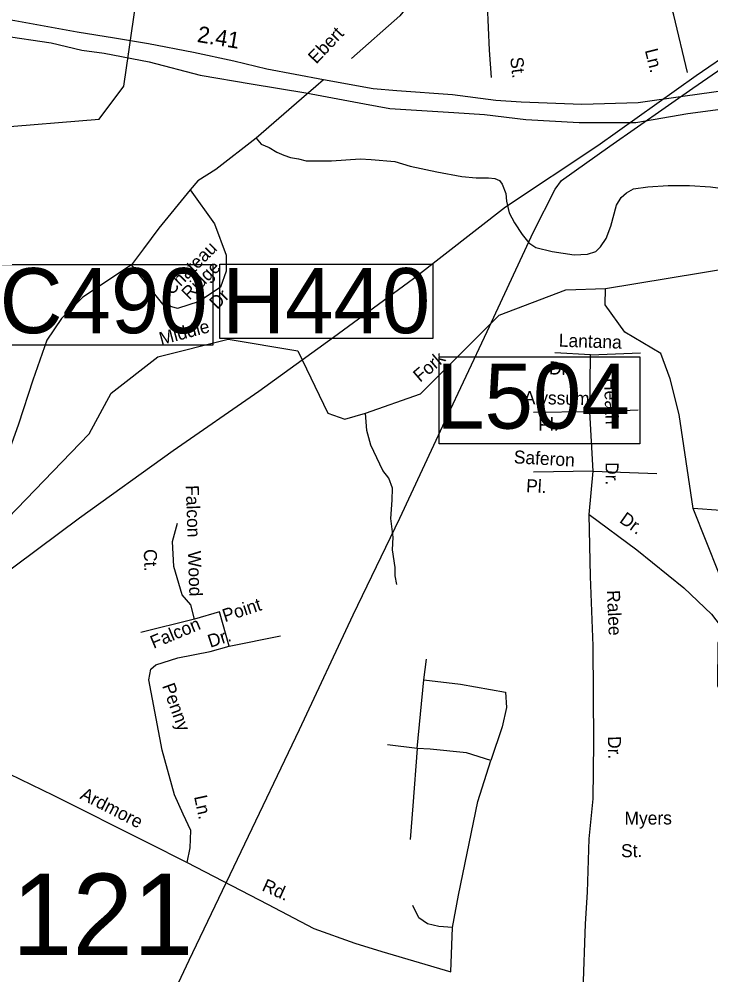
# Model space of a CAD drawing. Extents: x 1551653 to 1702041, y 811336 to 920032.
# Drawn here: x 1620272 to 1623759, y 839348 to 844163 of the extents above; entities that cross this region are included whole.
import ezdxf

# ---------------------------------------------------------------- set-up
doc = ezdxf.new("R2010")
doc.units = 0
for name, color, linetype in [('Old_Level_10', 7, 'Continuous'), ('Old_Level_11', 7, 'Continuous'), ('Old_Level_17', 7, 'Continuous'), ('Old_Level_21', 7, 'Continuous'), ('Old_Level_27', 7, 'Continuous'), ('Old_Level_31', 7, 'Continuous'), ('Old_Level_32', 7, 'Continuous'), ('Old_Level_35', 7, 'Continuous'), ('Old_Level_4', 7, 'Continuous'), ('Old_Level_50', 7, 'Continuous'), ('Old_Level_56', 7, 'Continuous'), ('Old_Level_59', 7, 'Continuous'), ('Old_Level_62', 7, 'Continuous')]:
    doc.layers.add(name, color=color, linetype=linetype)

msp = doc.modelspace()

# ---------------------------------------------------------------- linework, layer by layer
at = {"layer": 'Old_Level_27'}
for points in [[(1621806.298, 843856.608), (1621521.545, 843911.518), (1621354.108, 843951.408), (1621150.792, 843995.288), (1620923.556, 844039.166), (1620752.132, 844067.089), (1620564.607, 844097.349), (1620249.821, 844154.848), (1619925.289, 844210.557), (1619589.64, 844282.496), (1618684.683, 844462.002), (1618473.393, 844505.881), (1618317.916, 844533.804), (1618006.696, 844578.43)], [(1617998.162, 844491.323), (1618173.976, 844467.412), (1618325.894, 844448.624), (1618482.925, 844418.537), (1618628.87, 844386.21), (1618820.227, 844350.31), (1619111.249, 844294.463), (1619561.734, 844198.727), (1619807.309, 844146.869), (1619902.987, 844126.924), (1620034.544, 844102.991), (1620183.314, 844079.994), (1620433.204, 844043.155), (1620588.682, 844007.254), (1620700.307, 843991.298), (1620927.542, 843947.419), (1621185.29, 843881.285), (1621441.279, 843836.833), (1621716.888, 843791.847)], [(1624577.645, 844005.901), (1624379.138, 843949.014), (1624096.053, 843860.24), (1623834.931, 843802.799), (1623629.535, 843775.078), (1623392.767, 843742.06), (1623109.42, 843732.348), (1622802.439, 843743.979), (1622674.696, 843753.713), (1622457.335, 843780.905), (1622175.929, 843802.27), (1622056.945, 843811.792), (1621806.298, 843856.608)], [(1621716.888, 843791.847), (1622013.093, 843736.001), (1622140.664, 843712.067), (1622464.012, 843692.919), (1622617.791, 843682.659), (1622826.87, 843658.138), (1623094.506, 843641.619), (1623381.56, 843641.619), (1623642.632, 843687.587), (1623858.288, 843716.364), (1624130.854, 843767.233), (1624461.47, 843865.812), (1624631.119, 843917.611)]]:
    msp.add_lwpolyline(points, dxfattribs=at)
at = {"layer": 'Old_Level_31'}
for p, q in [((1620564.607, 844097.349), (1620564.607, 844097.349)), ((1620825.531, 843998.701), (1620825.531, 843998.701)), ((1621767.484, 843823.589), (1621767.484, 843823.589)), ((1622457.335, 843780.904), (1622457.335, 843780.904)), ((1622826.87, 843658.139), (1622826.87, 843658.139))]:
    msp.add_line(p, q, dxfattribs=at)
for points in [[(1620157.333, 842927.636), (1621249.32, 842927.636), (1621249.32, 842521.208), (1620157.333, 842521.208), (1620157.333, 842927.636)], [(1621283.748, 842927.973), (1622356.914, 842927.973), (1622356.914, 842553.337), (1621283.748, 842553.337), (1621283.748, 842927.973)], [(1622389.245, 842460.999), (1623400.299, 842460.999), (1623400.299, 842023.218), (1622389.245, 842023.218), (1622389.245, 842460.999)]]:
    msp.add_lwpolyline(points, dxfattribs=at)
at = {"layer": 'Old_Level_32'}
msp.add_lwpolyline([(1622500.494, 846737.982), (1622518.886, 846197.599), (1622529.488, 846013.418), (1622541.479, 845742.175), (1622554.294, 845524.149), (1622569.236, 845236.292), (1622579.853, 845113.503), (1622583.526, 844911.947), (1622569.474, 844778.609), (1622414.009, 844451.276), (1622191.029, 844179.385), (1621948.152, 843964.524)], dxfattribs=at)
at = {"layer": 'Old_Level_35'}
for p, q in [((1623152.508, 842472.175), (1622972.517, 842481.655)), ((1623149.35, 842184.596), (1623152.508, 842472.175)), ((1623152.508, 842472.175), (1623405.128, 842481.655)), ((1623149.35, 842184.596), (1622865.153, 842181.436)), ((1623149.35, 842184.596), (1623392.497, 842194.076)), ((1623165.156, 841885.486), (1623149.35, 842184.596)), ((1623165.156, 841885.486), (1622865.153, 841881.216)), ((1623146.21, 841667.432), (1623165.156, 841885.486)), ((1623165.156, 841885.486), (1623487.229, 841874.896)), ((1621282.75, 841177.692), (1621156.44, 841139.77)), ((1621330.176, 841005.072), (1621282.75, 841177.692)), ((1621156.44, 841139.77), (1620884.873, 841073.405)), ((1621330.176, 841005.072), (1621589.111, 841055.635)), ((1622312.882, 840834.567), (1622325.997, 840939.576)), ((1622277.91, 840488.914), (1622312.882, 840834.567)), ((1622277.91, 840488.914), (1622129.278, 840506.416)), ((1622448.399, 839364.448), (1622457.143, 839587.591))]:
    msp.add_line(p, q, dxfattribs=at)
for points in [[(1622575.768, 844799.691), (1622620.513, 844537.883), (1622630.838, 844234.737), (1622641.164, 844007.377), (1622651.489, 843869.582)], [(1623641.048, 843894.387), (1623572.193, 844183.053), (1623526.484, 844346.671), (1623480.407, 844506.892)], [(1621806.298, 843856.608), (1621767.484, 843823.59), (1621695.677, 843761.438), (1621466.671, 843563.326)], [(1621466.671, 843563.326), (1621262.894, 843406.003), (1621173.628, 843348.502), (1621134.873, 843303.252)], [(1621466.671, 843563.326), (1621492.036, 843533.79), (1621532.656, 843516.712), (1621571.47, 843493.405), (1621606.404, 843477.867), (1621639.396, 843466.214), (1621679.645, 843458.981), (1621719.017, 843449.132), (1621778.073, 843449.132), (1621846.973, 843449.132), (1621991.333, 843458.981), (1622047.109, 843455.699), (1622165.222, 843445.85), (1622243.964, 843422.869), (1622378.482, 843393.323), (1622503.157, 843370.342), (1622575.337, 843363.776), (1622637.675, 843363.776), (1622670.485, 843360.494), (1622693.45, 843350.645), (1622706.575, 843330.948), (1622726.26, 843284.986), (1622729.541, 843245.592), (1622742.665, 843186.499), (1622768.912, 843137.255), (1622808.283, 843078.163), (1622841.092, 843035.485), (1622877.182, 843012.504), (1622959.205, 842992.807), (1623070.757, 842976.392), (1623136.375, 842979.674), (1623179.028, 842992.807), (1623201.994, 843015.787), (1623231.522, 843058.464), (1623254.489, 843120.841), (1623284.017, 843225.894), (1623306.984, 843265.289), (1623333.231, 843288.27), (1623369.321, 843307.967), (1623441.501, 843317.816), (1623543.21, 843324.382), (1623651.48, 843324.382), (1623756.47, 843317.816), (1623881.145, 843301.401)], [(1621134.873, 843303.252), (1621257.598, 843131.95), (1621315.731, 842973.576), (1621315.731, 842892.773), (1621286.664, 842811.97), (1621180.087, 842740.863), (1621070.28, 842705.31), (1620996, 842727.934), (1620837.749, 842925.094)], [(1621134.873, 843303.252), (1620976.622, 843109.325), (1620899.111, 843005.897), (1620837.749, 842925.094)], [(1620837.749, 842925.094), (1620592.51, 842761.833), (1620485.933, 842655.173), (1620411.651, 842545.281), (1620340.6, 842344.889), (1620269.549, 842121.873), (1620208.186, 841953.802), (1620169.179, 841822.896)], [(1623108.371, 838931.79), (1623114.687, 839269.933), (1623127.318, 839604.915), (1623136.79, 839764.543), (1623146.264, 840033.16), (1623165.211, 840235.414), (1623168.314, 840518.576), (1623165.156, 841005.248), (1623152.525, 841354.571), (1623146.21, 841667.432)], [(1623146.21, 841667.432), (1623386.06, 841490.226), (1623622.891, 841297.453), (1623761.832, 841164.725), (1623910.246, 840971.952)], [(1621156.44, 841139.77), (1621137.493, 841212.454), (1621093.285, 841263.018), (1621052.234, 841405.227), (1621045.919, 841531.636), (1621071.181, 841623.282)], [(1621118.607, 839914.8), (1621134.396, 839987.486), (1621137.554, 840075.971), (1621099.661, 840158.136), (1621055.453, 840256.103), (1620992.297, 840480.478), (1620925.984, 840834.421), (1620935.458, 840888.145), (1620960.72, 840910.266), (1621071.241, 840945.028), (1621235.444, 840976.631), (1621330.176, 841005.072)], [(1619872.452, 840862.837), (1619962.872, 840739.615), (1620130.232, 840461.517), (1620221.807, 840360.39), (1620442.85, 840252.943), (1620919.67, 840015.927), (1621118.607, 839914.8)], [(1622312.882, 840834.567), (1622496.486, 840812.691), (1622723.806, 840773.312)], [(1622723.806, 840773.312), (1622728.176, 840694.556), (1622706.319, 840598.298), (1622649.489, 840427.659)], [(1622277.91, 840488.914), (1622256.052, 840200.141), (1622242.938, 840029.502)], [(1622649.489, 840427.659), (1622527.087, 840467.038), (1622343.483, 840484.539), (1622277.91, 840488.914)], [(1622457.143, 839587.591), (1622487.743, 839749.479), (1622583.917, 840222.018), (1622649.489, 840427.659)], [(1621118.607, 839914.8), (1621524.504, 839705.012), (1621758.177, 839581.764), (1621965.071, 839507.322), (1622100.854, 839466.24), (1622448.399, 839364.448)], [(1622457.143, 839587.591), (1622387.198, 839591.966), (1622330.368, 839605.092), (1622286.653, 839635.72), (1622256.052, 839696.975)]]:
    msp.add_lwpolyline(points, dxfattribs=at)
at = {"layer": 'Old_Level_50'}
msp.add_line((1620818.053, 843989.371), (1620818.053, 843989.371), dxfattribs=at)
at = {"layer": 'Old_Level_56'}
for points in [[(1621856.189, 842561.344), (1622260.401, 842856.914), (1622723.563, 843217.724), (1623190.068, 843526.237), (1623685.073, 843878.395), (1624078.96, 844148.358), (1624333.586, 844330.297)], [(1619581.164, 836149.7), (1619823.155, 836665.68), (1620060.704, 837159.94), (1620333.801, 837749.329), (1620608.702, 838338.885), (1620850.168, 838828.861), (1621129.347, 839422.134), (1621391.794, 839969.915), (1621685.225, 840585.111), (1621955.881, 841162.544), (1622191.461, 841648.639), (1622418.924, 842138.9), (1622631.775, 842589.434), (1622865.482, 843091.575), (1622974.881, 843305.676), (1623005.383, 843349.282), (1623250.045, 843523.418), (1623668.174, 843814.704), (1624084.226, 844102.226), (1624340.81, 844282.124)], [(1616465.16, 838628.458), (1616835.281, 838910.711), (1617201.313, 839178.841), (1617599.36, 839466.53), (1618007.614, 839764.217), (1618314.943, 839989.311), (1618545.441, 840155.732), (1618720.989, 840276.84), (1619161.775, 840599.881), (1619420.607, 840801.747), (1619780.685, 841072.196), (1620144.313, 841330.368), (1620577.058, 841651.572), (1621047.976, 841990.213), (1621480.271, 842289.215), (1621856.189, 842561.344)]]:
    msp.add_lwpolyline(points, dxfattribs=at)
at = {"layer": 'Old_Level_59'}
msp.add_line((1623227.766, 842805.535), (1624173.955, 842961.409), dxfattribs=at)
for points in [[(1619636.792, 841092.581), (1619735.729, 841635.559), (1619789.751, 841907.745), (1619954.195, 842180.808), (1620140.629, 843615.535), (1620676.27, 843658.265), (1620799.439, 843824.617), (1620825.531, 843998.701), (1620862.798, 844255.202), (1620958.891, 844645.714), (1620946.767, 844893.631), (1620790.722, 845097.043), (1620710.752, 845374.428), (1620725.721, 845882.905), (1620679.789, 846139.887), (1620614.787, 846282.347), (1620334.789, 846563.73), (1620230.725, 846913.805), (1620084.728, 847225.381), (1620088.726, 847507.585), (1620166.749, 847722.632)], [(1619636.792, 841092.581), (1619744.857, 841180.58), (1620031.828, 841460.322), (1620625.758, 842073.755), (1620735.301, 842278.063), (1620970.753, 842461.352), (1621325.801, 842551.126), (1621677.112, 842491.276), (1621828.323, 842177.193), (1621914.282, 842147.268), (1622018.928, 842177.193), (1622295.804, 842276.244), (1622691.521, 842672.121), (1623027.738, 842799.691), (1623227.766, 842805.535)], [(1623828.561, 840472.617), (1623841.795, 840695.447), (1623793.812, 840804.79), (1623795.76, 841021.377), (1623865.786, 841203.771), (1623669.254, 841697.201), (1623599.441, 842171.341), (1623553.364, 842351.661), (1623506.74, 842478.118), (1623324.756, 842586.898), (1623226.741, 842723.463), (1623227.766, 842805.535)]]:
    msp.add_lwpolyline(points, dxfattribs=at)
at = {"layer": 'Old_Level_62'}
for points in [[(1622175.951, 841314.394), (1622168.476, 841359.281), (1622168.476, 841400.427), (1622153.526, 841490.202), (1622157.264, 841553.791), (1622146.052, 841647.306), (1622152.19, 841740.551), (1622153.473, 841799.394), (1622136.493, 841850.591), (1622104.887, 841889.168), (1622074.988, 841952.758), (1622045.09, 842016.348), (1622025.616, 842091.18), (1622018.928, 842177.193)], [(1624222.769, 841362.808), (1624227.756, 841397.744), (1624187.863, 841462.627), (1624162.93, 841512.536), (1624118.051, 841557.455), (1624068.184, 841607.364), (1623948.505, 841677.237), (1623669.254, 841697.201)]]:
    msp.add_lwpolyline(points, dxfattribs=at)

# ---------------------------------------------------------------- texts
at = {"layer": 'Old_Level_10'}
for s, rotation, p in [('Ln.', 283.828558, (1623425.885, 844006.463)), ('St.', 276.725903, (1622746.967, 843968.726)), ('Chateau', 45.050444, (1621040.176, 842768.552)), ('Ridge', 45.050444, (1621130.189, 842744.635)), ('Dr.', 45.050444, (1621270.164, 842697.353)), ('Lantana', 358.108717, (1622991.824, 842513.189)), ('Dr.', 358.079783, (1622942.435, 842373.514)), ('Heath', 271.997097, (1623220.413, 842354.049)), ('Alyssum', 359.190706, (1622815.476, 842223.874)), ('Pl.', 359.190706, (1622888.592, 842090.348)), ('Saferon', 356.900506, (1622764.456, 841925.448)), ('Dr.', 270.07665, (1623228.038, 841931.48)), ('Pl.', 356.900506, (1622826.546, 841780.562)), ('Falcon', 272.002336, (1621111.925, 841814.319)), ('Dr.', 324.696697, (1623293.844, 841631.016)), ('Ct.', 272.002336, (1620900.086, 841492.289)), ('Wood', 272.002336, (1621122.581, 841483.124)), ('Ralee', 272.379567, (1623235.106, 841285.159)), ('Point', 18.142969, (1621309.334, 841124.623)), ('Falcon', 22.623403, (1620949.804, 840990.438)), ('Dr.', 18.142969, (1621235.505, 840995.707)), ('Penny', 289.634578, (1620991.819, 840804.678)), ('Dr.', 270.838181, (1623239.995, 840550.74)), ('Ardmore', 332.791814, (1620574.738, 840238.228)), ('Ln.', 282.338467, (1621153.363, 840246.314)), ('Myers', 0.398, (1623323.976, 840104.557)), ('St.', 0.398, (1623306.498, 839940.85)), ('Rd.', 335.966392, (1621491.643, 839775.292))]:
    msp.add_text(s, height=65.6167, rotation=rotation, dxfattribs=at).set_placement(p)
at = {"layer": 'Old_Level_11'}
msp.add_text('Ebert', height=65.6167, rotation=46.542408, dxfattribs=at).set_placement((1621769.48, 843933.798))
at = {"layer": 'Old_Level_17'}
msp.add_text('2.41', height=82.0208, rotation=350.526581, dxfattribs=at).set_placement((1621165.933, 844048.579))
at = {"layer": 'Old_Level_21'}
for s, rotation, p in [('Middle', 15.048614, (1620988, 842519.999)), ('Fork', 40.674103, (1622293.197, 842330.939))]:
    msp.add_text(s, height=65.6167, rotation=rotation, dxfattribs=at).set_placement(p)
at = {"layer": 'Old_Level_31'}
for s, p in [('C490', (1620173.751, 842580.847)), ('H440', (1621295.731, 842580.869)), ('L504', (1622374.062, 842100.099))]:
    msp.add_text(s, height=328.0833, dxfattribs=at).set_placement(p)
at = {"layer": 'Old_Level_4'}
msp.add_text('121', height=410.1042, dxfattribs=at).set_placement((1620235.837, 839448.254))

doc.saveas('drawing.dxf')
